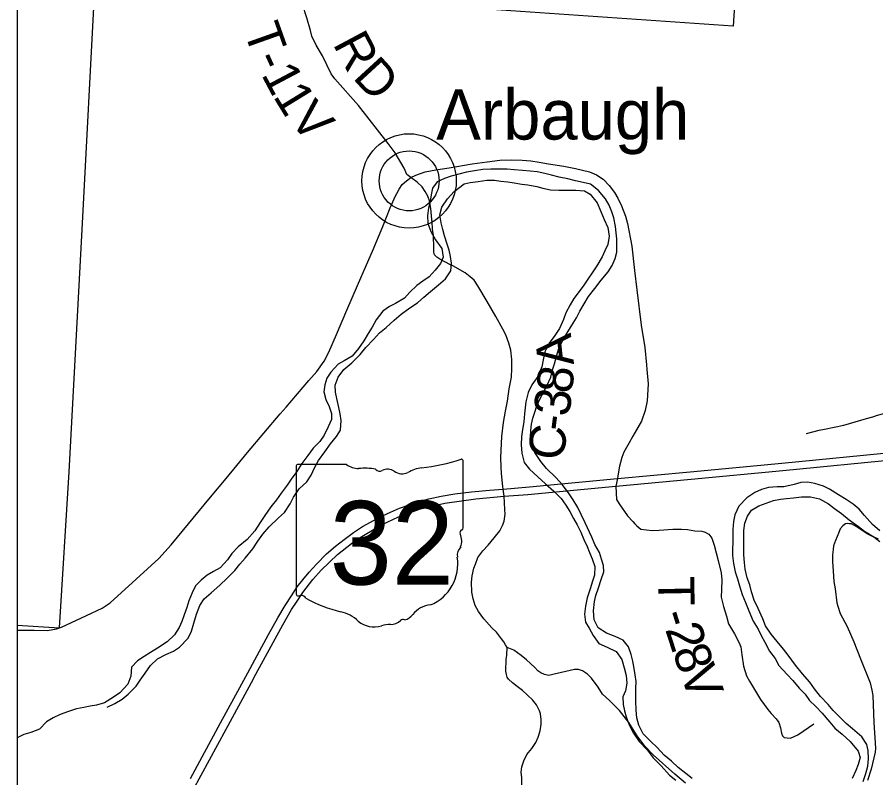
# Model space of a CAD drawing. Extents: x 0 to 34, y 0 to 22.
# Drawn here: x 2.1 to 3.455, y 17.798 to 18.997 of the extents above; entities that cross this region are included whole.
import ezdxf

# ---------------------------------------------------------------- set-up
doc = ezdxf.new("R2010")
doc.units = 0
for name, color, linetype in [('GM_X_Corporation', 7, 'Continuous'), ('GM_X_County_Road', 7, 'Continuous'), ('GM_X_County_Road_Text', 7, 'Continuous'), ('GM_X_Major_River', 7, 'Continuous'), ('GM_X_State_Location', 7, 'Continuous'), ('GM_X_State_Route', 7, 'Continuous'), ('GM_X_State_Shield', 7, 'Continuous'), ('GM_X_Township_Road', 7, 'Continuous'), ('GM_X_Township_Road_Text', 7, 'Continuous'), ('GM_X_Unincorporated', 7, 'Continuous'), ('GM_X_Unincorporated_Location', 7, 'Continuous'), ('GM_X_Unincorporated_Text', 7, 'Continuous'), ('SH_Data', 7, 'Continuous')]:
    doc.layers.add(name, color=color, linetype=linetype)

msp = doc.modelspace()

# ---------------------------------------------------------------- linework, layer by layer
at = {"layer": 'GM_X_Corporation'}
msp.add_lwpolyline([(4.1215, 17.0136), (4.1603, 17.6679), (4.1853, 18.0392), (4.1964, 18.2095), (4.2079, 18.3668), (4.2088, 18.3789), (4.2282, 18.6426), (4.2537, 18.9868), (4.2536, 19.0552), (4.2737, 19.3421), (4.2893, 19.6309), (4.3029, 19.8336), (4.3134, 19.9898), (4.3401, 20.3869), (4.364, 20.7926), (4.3772, 20.9), (2.1, 20.9), (2.1, 14.9497)], dxfattribs=at)
for points in [[(2.3005, 20.0682), (3.2948, 19.9968), (3.2295, 18.9829), (2.2229, 19.053)], [(2.1, 19.0613), (2.1, 18.0382), (2.1667, 18.0342), (2.1822, 18.2802), (2.2023, 18.6627), (2.2229, 19.053)]]:
    msp.add_lwpolyline(points, close=True, dxfattribs=at)
at = {"layer": 'GM_X_County_Road'}
for points in [[(2.1, 18.0305), (2.1267, 18.0305), (2.1481, 18.0299), (2.1621, 18.0324), (2.1702, 18.0351), (2.1859, 18.0427), (2.2093, 18.0539), (2.2342, 18.0655), (2.2466, 18.0734), (2.288, 18.111), (2.3237, 18.1436), (2.3432, 18.1649), (2.4051, 18.2402), (2.4295, 18.2695), (2.4635, 18.3107), (2.5151, 18.3719), (2.5242, 18.3825), (2.5602, 18.4245), (2.5726, 18.4387), (2.5843, 18.4547), (2.5917, 18.4691), (2.6041, 18.4969), (2.6202, 18.5351), (2.6368, 18.5741), (2.651, 18.6067), (2.6605, 18.6283), (2.6768, 18.667), (2.6887, 18.6965), (2.6968, 18.7154), (2.6988, 18.7191), (2.7028, 18.7263), (2.7076, 18.7334), (2.7143, 18.739), (2.721, 18.7446), (2.7292, 18.7481), (2.7436, 18.7535), (2.7605, 18.7564), (2.7817, 18.7597), (2.8181, 18.7659), (2.8416, 18.769), (2.8613, 18.7717), (2.8807, 18.7724), (2.8968, 18.7717), (2.9107, 18.7705), (2.9237, 18.7685), (2.9386, 18.7662), (2.9625, 18.7621), (2.981, 18.7587), (3.0032, 18.7535), (3.0142, 18.7487), (3.0246, 18.7419), (3.0339, 18.7318), (3.0425, 18.721), (3.0477, 18.7116), (3.0535, 18.7), (3.0598, 18.6836), (3.0631, 18.6719), (3.0699, 18.6359), (3.0742, 18.5979), (3.0779, 18.5674), (3.0847, 18.5118), (3.0906, 18.4762), (3.093, 18.449)], [(2.7547, 18.6743), (2.7544, 18.6784), (2.7529, 18.6955), (2.7507, 18.7075), (2.7477, 18.7151), (2.744, 18.7225), (2.7388, 18.7295), (2.7312, 18.7371), (2.721, 18.7446)], [(2.7838, 18.6069), (2.7671, 18.6156), (2.7619, 18.6186), (2.7585, 18.6224), (2.7574, 18.6267), (2.7572, 18.6331), (2.7567, 18.6533), (2.7555, 18.663), (2.7547, 18.6743)], [(2.8684, 18.2419), (2.8669, 18.253), (2.8663, 18.257), (2.8644, 18.2778), (2.8639, 18.2876), (2.8629, 18.3026), (2.8647, 18.3362), (2.8676, 18.3582), (2.8706, 18.376), (2.8734, 18.3917), (2.8762, 18.411), (2.8799, 18.4295), (2.8807, 18.4434), (2.8804, 18.4576), (2.8788, 18.4721), (2.876, 18.4833), (2.871, 18.4964), (2.8663, 18.5055), (2.8554, 18.5253), (2.8415, 18.5488), (2.8269, 18.5738), (2.8213, 18.5826), (2.8149, 18.588), (2.8069, 18.5943), (2.7873, 18.6051), (2.7838, 18.6069)], [(3.093, 18.449), (3.0937, 18.4419), (3.0955, 18.419), (3.094, 18.3921), (3.0907, 18.3769), (3.0852, 18.36), (3.0713, 18.3364), (3.0658, 18.3261), (3.0572, 18.3111), (3.0538, 18.3028), (3.0503, 18.2894), (3.0478, 18.2737), (3.0471, 18.27), (3.0447, 18.2579)], [(2.8361, 18.0485), (2.8277, 18.0601), (2.8228, 18.0696), (2.8195, 18.0797), (2.8174, 18.0904), (2.817, 18.1064), (2.8178, 18.1163), (2.8203, 18.1285), (2.8233, 18.1348), (2.8268, 18.145), (2.8346, 18.1557), (2.8431, 18.1648), (2.8525, 18.1763), (2.8614, 18.1873), (2.8658, 18.1957), (2.8685, 18.2027), (2.8698, 18.2134), (2.8694, 18.2208), (2.8684, 18.2419)], [(2.8733, 18.0032), (2.8704, 18.0072), (2.8677, 18.0119), (2.8641, 18.0169), (2.8563, 18.0275), (2.8487, 18.0344), (2.8361, 18.0485)], [(2.8963, 17.7854), (2.8962, 17.7978), (2.8954, 17.8066), (2.8965, 17.8148), (2.8995, 17.8246), (2.9042, 17.8344), (2.9123, 17.844), (2.9183, 17.8534), (2.9223, 17.8618), (2.9253, 17.8719), (2.927, 17.8823), (2.9268, 17.8896), (2.9255, 17.8984), (2.9239, 17.9035), (2.9192, 17.9126), (2.9131, 17.9207), (2.9053, 17.9279), (2.8971, 17.9352), (2.8889, 17.9419), (2.8815, 17.9475), (2.8753, 17.9533), (2.8732, 17.9562), (2.8721, 17.9608), (2.8712, 17.9657), (2.871, 17.9718), (2.8716, 17.9789), (2.8718, 17.9843), (2.8727, 17.9911), (2.8733, 18.0032)]]:
    msp.add_lwpolyline(points, dxfattribs=at)
at = {"layer": 'GM_X_Major_River'}
for points in [[(3.0433, 18.6165), (3.0464, 18.6267), (3.0464, 18.6362), (3.046, 18.6476), (3.0453, 18.6571), (3.0442, 18.6673), (3.0415, 18.681), (3.0385, 18.6905), (3.0339, 18.7007), (3.0283, 18.711), (3.0173, 18.7239), (3.0044, 18.7338), (2.993, 18.7368), (2.9808, 18.7391), (2.9687, 18.7421), (2.9554, 18.7452), (2.9429, 18.7482), (2.9326, 18.7505), (2.9205, 18.7532), (2.9095, 18.7547), (2.8973, 18.7555), (2.884, 18.7566), (2.873, 18.7574), (2.8476, 18.7574), (2.835, 18.757), (2.8217, 18.7552), (2.8092, 18.7529), (2.7967, 18.7499), (2.7849, 18.7465), (2.7743, 18.7431), (2.7629, 18.7378), (2.7553, 18.7275), (2.753, 18.7169), (2.7514, 18.707), (2.7491, 18.696), (2.7476, 18.6843), (2.748, 18.6721), (2.7525, 18.6592), (2.7601, 18.6463), (2.77, 18.6326), (2.7722, 18.619), (2.7677, 18.6087), (2.7597, 18.5985), (2.7498, 18.5879), (2.7403, 18.5807), (2.7308, 18.5742), (2.7198, 18.5636), (2.7114, 18.5541), (2.697, 18.5458), (2.6875, 18.5409), (2.6772, 18.5337), (2.6666, 18.52), (2.6601, 18.5086), (2.654, 18.4984), (2.6468, 18.4866), (2.6388, 18.4749), (2.6285, 18.4628), (2.616, 18.4555), (2.6065, 18.4499), (2.5951, 18.4374), (2.5886, 18.4279), (2.5856, 18.4176), (2.5841, 18.4062), (2.5871, 18.3941), (2.5924, 18.3831), (2.5962, 18.3725), (2.5958, 18.363), (2.5908, 18.3512), (2.5844, 18.3383), (2.5775, 18.3281), (2.5669, 18.3175), (2.5585, 18.3061), (2.5494, 18.2932), (2.541, 18.281), (2.5323, 18.2685), (2.5258, 18.2591), (2.5167, 18.2465), (2.5091, 18.2359), (2.5003, 18.2253), (2.4908, 18.2116), (2.4836, 18.2003), (2.4748, 18.187), (2.4627, 18.1737), (2.4486, 18.162), (2.4387, 18.1517), (2.4319, 18.1415), (2.4205, 18.1286), (2.4099, 18.1233), (2.3996, 18.1172), (2.3901, 18.1096), (2.3813, 18.1002), (2.376, 18.0892), (2.3707, 18.077), (2.3676, 18.0664), (2.3635, 18.0546), (2.3596, 18.0444), (2.3558, 18.0349), (2.3482, 18.0231), (2.3365, 18.0121), (2.3216, 18.0023), (2.3102, 17.9951)], [(2.2418, 17.909), (2.2543, 17.9147), (2.2657, 17.9219), (2.2752, 17.9295), (2.2878, 17.942), (2.2939, 17.9515), (2.3018, 17.9625), (2.3106, 17.975), (2.3212, 17.9852), (2.3345, 17.992), (2.3467, 17.9973), (2.3562, 18.0038), (2.3699, 18.0178), (2.3752, 18.0288), (2.379, 18.0417), (2.3828, 18.0558), (2.3882, 18.0694), (2.395, 18.08), (2.406, 18.0895), (2.4197, 18.1016), (2.4315, 18.1126), (2.4436, 18.1244), (2.4513, 18.1346), (2.4596, 18.1441), (2.4718, 18.1589), (2.4798, 18.1707), (2.4874, 18.182), (2.4976, 18.1934), (2.5121, 18.2078), (2.522, 18.2162), (2.5307, 18.2298), (2.536, 18.2401), (2.5452, 18.2533), (2.5569, 18.2647), (2.5638, 18.275), (2.5691, 18.2867), (2.5752, 18.2981), (2.5855, 18.3118), (2.5942, 18.3243), (2.6041, 18.336), (2.6102, 18.3459), (2.611, 18.3611), (2.6098, 18.3717), (2.6076, 18.3819), (2.6042, 18.396), (2.6023, 18.4059), (2.6019, 18.4169), (2.6065, 18.4294), (2.6156, 18.4415), (2.6281, 18.4521), (2.6411, 18.4654), (2.6502, 18.4764), (2.6624, 18.4889), (2.6719, 18.4995), (2.6821, 18.5079), (2.695, 18.5196), (2.7057, 18.5287), (2.7197, 18.539), (2.7315, 18.5469), (2.7414, 18.5556), (2.7524, 18.5644), (2.765, 18.575), (2.776, 18.5844), (2.784, 18.597), (2.7851, 18.6095), (2.7836, 18.6201), (2.7817, 18.6296), (2.7787, 18.6391), (2.7742, 18.6524), (2.7715, 18.6622), (2.7689, 18.6729), (2.767, 18.6854), (2.77, 18.6979), (2.7788, 18.7108), (2.7894, 18.7226), (2.8054, 18.7347), (2.8149, 18.7366), (2.8274, 18.7381), (2.8411, 18.74), (2.8529, 18.7403), (2.8631, 18.7388), (2.8741, 18.7377), (2.884, 18.7361), (2.8961, 18.7339), (2.906, 18.7327), (2.9197, 18.7304), (2.9295, 18.7278), (2.9417, 18.7251), (2.9546, 18.7243), (2.9816, 18.7243), (2.9949, 18.7232), (3.0043, 18.7182), (3.015, 18.7045), (3.021, 18.6909), (3.0263, 18.678), (3.032, 18.6654), (3.0343, 18.6518), (3.032, 18.6389), (3.0274, 18.629), (3.0232, 18.6195), (3.0145, 18.6051)], [(3.1648, 17.7967), (3.1549, 17.8047), (3.1428, 17.8138), (3.1322, 17.8237), (3.1211, 17.8336), (3.1098, 17.8453), (3.0999, 17.8548), (3.0878, 17.867), (3.0809, 17.8807), (3.0779, 17.8924), (3.0768, 17.9042), (3.076, 17.919), (3.0761, 17.9285), (3.0764, 17.9387), (3.0765, 17.9497), (3.0753, 17.96), (3.0734, 17.9702), (3.0712, 17.9816), (3.0689, 17.9922), (3.0644, 18.0044), (3.056, 18.0146), (3.0435, 18.0207), (3.0298, 18.0257), (3.0169, 18.034), (3.0105, 18.0469), (3.0094, 18.061), (3.0109, 18.0758), (3.0132, 18.0852), (3.0174, 18.0974), (3.0216, 18.1107), (3.0254, 18.1224), (3.025, 18.1323), (3.022, 18.1425), (3.0186, 18.1528), (3.0117, 18.1657), (3.0068, 18.1771), (2.9962, 18.1999), (2.9898, 18.2132), (2.9848, 18.2242), (2.9773, 18.2359), (2.9708, 18.2458), (2.9606, 18.2595), (2.95, 18.2712), (2.9352, 18.2857), (2.9264, 18.2963), (2.917, 18.3107), (2.9105, 18.324), (2.9102, 18.3354), (2.9105, 18.3453), (2.9117, 18.3555), (2.9136, 18.365), (2.9167, 18.3745), (2.9197, 18.3844), (2.9254, 18.3961), (2.9307, 18.406), (2.9364, 18.417), (2.9418, 18.4295), (2.9444, 18.4409), (2.9479, 18.4504), (2.9509, 18.4625), (2.9547, 18.475), (2.9612, 18.4879), (2.9673, 18.4982), (2.9749, 18.5103), (2.9825, 18.5232), (2.9878, 18.5338), (3.0015, 18.5566), (3.0114, 18.5695), (3.0217, 18.5827), (3.0323, 18.5956), (3.0388, 18.6059), (3.0433, 18.6165)], [(3.0145, 18.6051), (3.0084, 18.5956), (3.0004, 18.5843), (2.9939, 18.5744), (2.9867, 18.5645), (2.9784, 18.5535), (2.9723, 18.5437), (2.9658, 18.5308), (2.962, 18.5206), (2.9555, 18.5065), (2.9483, 18.4951), (2.9392, 18.4834), (2.9327, 18.4697), (2.93, 18.4568), (2.9277, 18.4458), (2.9216, 18.4306), (2.9121, 18.4174), (2.9061, 18.4052), (2.9026, 18.3908), (2.9015, 18.3813), (2.9007, 18.3718), (2.8992, 18.3589), (2.8973, 18.3472), (2.8957, 18.3358), (2.8953, 18.3229), (2.8965, 18.3096), (2.9002, 18.2948), (2.9082, 18.2846), (2.9215, 18.2724), (2.9336, 18.2614), (2.9469, 18.2496), (2.9583, 18.2382), (2.9655, 18.2276), (2.9719, 18.2177), (2.978, 18.2067), (2.9837, 18.1965), (2.9894, 18.1851), (2.9943, 18.1737), (2.9992, 18.1627), (3.003, 18.1528), (3.0072, 18.1429), (3.0113, 18.1312), (3.0109, 18.1171), (3.0079, 18.1076), (3.0041, 18.0955), (2.9991, 18.0815), (2.9965, 18.0686), (2.9949, 18.056), (2.9968, 18.0431), (3.0025, 18.0336), (3.0089, 18.0223), (3.018, 18.0097), (3.0309, 18.0036), (3.045, 17.9968), (3.0541, 17.9843), (3.0579, 17.9714), (3.0609, 17.9592), (3.062, 17.9467), (3.0597, 17.9349), (3.0559, 17.9254), (3.0563, 17.9133), (3.0582, 17.9034), (3.0608, 17.8939), (3.0654, 17.8814), (3.0726, 17.8681), (3.0813, 17.8552), (3.0938, 17.8416), (3.1033, 17.829), (3.1162, 17.8165), (3.1291, 17.8017), (3.1393, 17.7941)], [(3.4614, 18.1874), (3.4496, 18.1972), (3.4367, 18.2113), (3.4287, 18.2212), (3.4192, 18.2291), (3.4079, 18.2367), (3.3961, 18.244), (3.3817, 18.2531), (3.3722, 18.2576), (3.3585, 18.2618), (3.3468, 18.2637), (3.3365, 18.2634), (3.3259, 18.2603), (3.3095, 18.2565), (3.2993, 18.2566), (3.2856, 18.2558), (3.2746, 18.2524), (3.264, 18.2479), (3.2514, 18.2391), (3.2389, 18.2259), (3.2324, 18.2122), (3.2301, 18.202), (3.2294, 18.1894), (3.229, 18.1792), (3.2289, 18.1485), (3.2304, 18.1356), (3.2331, 18.1227), (3.2365, 18.1113), (3.2399, 18.1006), (3.2441, 18.0866), (3.2494, 18.0741), (3.2547, 18.0608), (3.2615, 18.0445), (3.2691, 18.0323), (3.274, 18.0221), (3.2797, 18.0114), (3.2872, 17.9974), (3.296, 17.9856), (3.302, 17.9746), (3.3149, 17.9605), (3.324, 17.9511), (3.3339, 17.9389), (3.3434, 17.9298), (3.3502, 17.9195), (3.3604, 17.9104), (3.3703, 17.8998), (3.3824, 17.8854), (3.3904, 17.8759), (3.4018, 17.8667), (3.4143, 17.855)], [(3.4424, 17.8162), (3.4435, 17.8276), (3.4428, 17.8409), (3.4405, 17.8504), (3.4325, 17.8625), (3.4181, 17.8747), (3.4079, 17.8831), (3.3984, 17.8926), (3.3874, 17.9039), (3.3798, 17.9134), (3.3677, 17.926), (3.3582, 17.9381), (3.3506, 17.9484), (3.3392, 17.9617), (3.3279, 17.9753), (3.3165, 17.9909), (3.3093, 18.0008), (3.299, 18.0125), (3.2899, 18.0243), (3.2808, 18.0376), (3.2763, 18.0482), (3.2691, 18.0649), (3.263, 18.0778), (3.2589, 18.0911), (3.2558, 18.1021), (3.2517, 18.1132), (3.2487, 18.1268), (3.2475, 18.1374), (3.2468, 18.1496), (3.2464, 18.161), (3.2464, 18.1761), (3.2468, 18.1875), (3.248, 18.1993), (3.2525, 18.2103), (3.2586, 18.2198), (3.2704, 18.2266), (3.2818, 18.2308), (3.2936, 18.2353), (3.3042, 18.2372), (3.3137, 18.238), (3.3251, 18.2391), (3.3376, 18.241), (3.3517, 18.2406), (3.3661, 18.2375), (3.3801, 18.2296), (3.3896, 18.2223), (3.4006, 18.2144), (3.4128, 18.2045), (3.4276, 18.1938), (3.4371, 18.1866), (3.4515, 18.1775), (3.461, 18.1703)], [(2.3102, 17.9951), (2.3004, 17.989), (2.2901, 17.9822), (2.2806, 17.972), (2.2791, 17.9579), (2.2745, 17.9454), (2.2619, 17.9317), (2.2521, 17.9249), (2.2376, 17.9162), (2.2251, 17.9124), (2.2152, 17.9105), (2.205, 17.9086), (2.1936, 17.9064), (2.181, 17.9022), (2.1677, 17.8977), (2.1567, 17.8924), (2.1465, 17.8859), (2.1351, 17.8742), (2.1214, 17.8692), (2.1104, 17.8658), (2.1, 17.8608)], [(3.4143, 17.855), (3.4268, 17.8398), (3.4299, 17.8299), (3.4272, 17.8185), (3.4234, 17.809), (3.4177, 17.7965)], [(3.4348, 17.792), (3.4393, 17.8045), (3.4424, 17.8162)]]:
    msp.add_lwpolyline(points, dxfattribs=at)
at = {"layer": 'GM_X_State_Route'}
for points in [[(2.3735, 17.7966), (2.421, 17.8843), (2.4418, 17.9229), (2.4641, 17.9632), (2.4786, 17.9904), (2.4964, 18.0236), (2.5112, 18.0502), (2.5227, 18.0695), (2.5327, 18.0848), (2.5418, 18.0988), (2.5505, 18.1098), (2.5607, 18.122), (2.5725, 18.1346), (2.588, 18.1507), (2.6023, 18.1629), (2.616, 18.1733), (2.6308, 18.1845), (2.6449, 18.1942), (2.6633, 18.2039), (2.6762, 18.211), (2.6888, 18.2167), (2.7035, 18.2231), (2.7183, 18.2284), (2.7326, 18.2332), (2.7494, 18.2378), (2.7689, 18.2419), (2.7905, 18.2457), (2.817, 18.2486), (2.8454, 18.2514), (2.8669, 18.253), (2.9082, 18.2567), (3.0471, 18.27), (3.1619, 18.2802), (3.3064, 18.2941), (3.4888, 18.3117)], [(2.3774, 17.7779), (2.4297, 17.8746), (2.4727, 17.954), (2.4735, 17.9555), (2.519, 18.0388), (2.5328, 18.0629), (2.5418, 18.0764), (2.5508, 18.0899), (2.5667, 18.1102), (2.5796, 18.125), (2.6054, 18.1498), (2.6351, 18.1729), (2.6746, 18.1969), (2.7018, 18.2094), (2.7365, 18.2218), (2.7747, 18.2311), (2.8239, 18.2377), (2.8684, 18.2419), (2.9058, 18.2447), (3.0447, 18.2579), (3.1634, 18.2685), (3.3079, 18.2824), (3.4904, 18.3)]]:
    msp.add_lwpolyline(points, dxfattribs=at)
at = {"layer": 'GM_X_State_Shield'}
for p, q in [((2.6198, 18.2918), (2.5426, 18.2918)), ((2.8036, 18.1921), (2.8036, 18.2968)), ((2.54, 18.2884), (2.54, 18.0883)), ((2.8036, 18.1921), (2.8036, 18.1921))]:
    msp.add_line(p, q, dxfattribs=at)
for centre, radius, start, end in [((2.543, 18.2888), 0.00305, 98.1301, 188.1301), ((2.6382, 18.3151), 0.0296, 231.6195, 271.1119), ((2.7097, 18.5647), 0.2796, 275.8445, 288.9065), ((2.8007, 18.2972), 0.00294, 351.8621, 97.738), ((2.648, 18.1795), 0.1064, 80.4867, 94.9883), ((2.6722, 18.2899), 0.00855, 219.7921, 297.1024), ((2.6847, 18.2667), 0.0178, 54.4667, 119.1411), ((2.7076, 18.2985), 0.0214, 233.8562, 294.8282), ((2.7454, 18.2307), 0.0563, 97.3462, 120.7689), ((2.803, 18.1844), 0.00454, 107.944, 210.337), ((2.7741, 18.1712), 0.0273, 340.033, 23.6496), ((2.8005, 18.1917), 0.00314, 289.6038, 7.7341), ((2.8142, 18.1483), 0.0198, 136.8065, 186.9296), ((2.7254, 18.135), 0.0699, 292.3089, 8.9858), ((2.543, 18.0878), 0.00308, 171.9584, 258.3066), ((2.5435, 18.1083), 0.0235, 267.339, 280.6039), ((2.5483, 18.0767), 0.00848, 29.7484, 93.2717), ((2.6554, 18.2565), 0.2019, 240.4129, 257.1985), ((2.7549, 18.0321), 0.0383, 94.4031, 142.5768), ((2.5952, 17.9984), 0.0632, 47.1842, 75.836), ((2.7089, 18.0414), 0.00601, 65.7517, 132.6484), ((2.7064, 18.0689), 0.0226, 282.8732, 323.2771), ((2.6635, 18.0757), 0.0401, 230.7004, 286.2918), ((2.6867, 18.0066), 0.0329, 85.6951, 111.2099), ((2.6896, 18.0608), 0.0214, 268.777, 315.5493)]:
    msp.add_arc(centre, radius, start, end, dxfattribs=at)
at = {"layer": 'GM_X_Township_Road'}
for points in [[(2.721, 18.7446), (2.715, 18.7492), (2.7106, 18.7591), (2.6963, 18.7836), (2.6856, 18.7982), (2.6387, 18.8579), (2.6011, 18.9), (2.5956, 18.9081), (2.5886, 18.9223), (2.5817, 18.9363), (2.5719, 18.9531), (2.5647, 18.9671), (2.5626, 18.9765), (2.5573, 18.9965), (2.55, 19.0171)], [(3.3454, 18.3407), (3.3656, 18.3459), (3.374, 18.3477), (3.4041, 18.354), (3.4403, 18.3643), (3.4503, 18.3671), (3.4576, 18.3694), (3.4673, 18.372)], [(3.0447, 18.2579), (3.0453, 18.2464), (3.0459, 18.2364), (3.0497, 18.2296), (3.0631, 18.211), (3.0713, 18.2018), (3.0745, 18.1984)], [(3.0745, 18.1984), (3.0777, 18.195), (3.0839, 18.19), (3.0931, 18.1886), (3.1021, 18.1876), (3.1129, 18.1882), (3.1347, 18.1896), (3.1481, 18.1896), (3.1577, 18.1892), (3.1695, 18.1874), (3.1803, 18.1866), (3.1857, 18.1852), (3.1893, 18.1831)], [(3.459, 18.1743), (3.4483, 18.1789), (3.441, 18.1825), (3.4246, 18.1937), (3.4162, 18.1981), (3.413, 18.1982), (3.4108, 18.1989), (3.4071, 18.1982), (3.4025, 18.1949), (3.3987, 18.1902), (3.3966, 18.1847), (3.3937, 18.1783), (3.3912, 18.1722), (3.3882, 18.1637), (3.3874, 18.1577), (3.3867, 18.1496), (3.3867, 18.1389), (3.3877, 18.1238), (3.3886, 18.1075), (3.3906, 18.0956), (3.3935, 18.0739), (3.395, 18.0683), (3.3987, 18.057), (3.4095, 18.0361), (3.4199, 18.012), (3.4307, 17.9852), (3.4457, 17.9474), (3.4487, 17.9361), (3.45, 17.9277), (3.4515, 17.8847), (3.4542, 17.8446), (3.4539, 17.8383), (3.4475, 17.8113), (3.4417, 17.7936)], [(3.1893, 18.1831), (3.1911, 18.182), (3.1963, 18.1754), (3.1997, 18.1646), (3.2059, 18.1404), (3.2106, 18.121), (3.2119, 18.1098), (3.2111, 18.0946), (3.2106, 18.0826), (3.2143, 18.068), (3.219, 18.0528), (3.2225, 18.0406), (3.2318, 18.0249), (3.2388, 18.0118), (3.242, 18.0042), (3.2434, 17.9918), (3.246, 17.9738), (3.2508, 17.9585), (3.2556, 17.9501), (3.273, 17.9211), (3.2842, 17.9053), (3.2896, 17.8993), (3.2974, 17.8905), (3.3016, 17.8847), (3.3044, 17.8763), (3.3062, 17.8681), (3.3076, 17.8639), (3.3102, 17.8612), (3.315, 17.8605), (3.3204, 17.8601), (3.3316, 17.8653), (3.357, 17.8827)], [(3.1547, 17.7891), (3.1376, 17.8037), (3.1033, 17.8341), (3.091, 17.847), (3.0784, 17.8641), (3.0652, 17.885), (3.0502, 17.9039), (3.0348, 17.9195), (3.0235, 17.9294), (3.0165, 17.9405), (3.0061, 17.9547), (3, 17.9611), (2.9921, 17.9664), (2.9857, 17.9684), (2.9795, 17.9686), (2.9586, 17.964), (2.9473, 17.9611), (2.939, 17.9591), (2.932, 17.9608), (2.9265, 17.9632), (2.9215, 17.9663), (2.9168, 17.9718), (2.9035, 17.9838), (2.8954, 17.9905), (2.8837, 17.9988), (2.8733, 18.0032)]]:
    msp.add_lwpolyline(points, dxfattribs=at)
at = {"layer": 'GM_X_Unincorporated'}
for radius in [0.0744, 0.0472]:
    msp.add_circle((2.7184, 18.7391), radius, dxfattribs=at)
at = {"layer": 'GM_X_Unincorporated_Location'}
msp.add_line((2.7184, 18.7391), (2.7184, 18.7391), dxfattribs=at)
at = {"layer": 'SH_Data'}
msp.add_line((2.1, 20.9), (2.1, 14.1), dxfattribs=at)

# ---------------------------------------------------------------- texts
at = {"layer": 'GM_X_County_Road_Text'}
for s, rotation, p in [('A', 95.9709, (2.9787, 18.4499)), ('8', 84.4097, (2.9754, 18.4026)), ('3', 82.6442, (2.9707, 18.366)), ('-', 82.5248, (2.9676, 18.3427)), ('C', 82.4848, (2.9615, 18.2964))]:
    msp.add_text(s, height=0.0568, rotation=rotation, dxfattribs=at).set_placement(p)
at = {"layer": 'GM_X_State_Location'}
for s in ['s', 'r']:
    msp.add_text(s, height=0.000189, dxfattribs=at).set_placement((2.6688, 18.175))
msp.add_text('32', height=0.000189, rotation=0, dxfattribs=at).set_placement((2.6212, 18.1613))
at = {"layer": 'GM_X_State_Shield'}
msp.add_text('32', height=0.13184, dxfattribs=at).set_placement((2.5931, 18.1024))
at = {"layer": 'GM_X_Township_Road_Text'}
for s, rotation, p in [('T', 289.606, (2.457, 18.9765)), ('R', 298.0629, (2.5973, 18.9553)), ('-', 294.4269, (2.4732, 18.9317)), ('D', 312.5156, (2.6281, 18.9016)), ('1', 297.8754, (2.4845, 18.9071)), ('1', 301.5417, (2.5029, 18.8727)), ('V', 311.4533, (2.5275, 18.8343)), ('T', 271.0886, (3.1114, 18.1149)), ('-', 287.1894, (3.1149, 18.0553)), ('2', 287.9924, (3.1221, 18.0322)), ('8', 289.0056, (3.1333, 17.9978)), ('V', 289.8755, (3.145, 17.9639))]:
    msp.add_text(s, height=0.0568, rotation=rotation, dxfattribs=at).set_placement(p)
at = {"layer": 'GM_X_Unincorporated_Text'}
msp.add_text('Arbaugh', height=0.07898, rotation=0, dxfattribs=at).set_placement((2.7612, 18.8043))

doc.saveas('drawing.dxf')
